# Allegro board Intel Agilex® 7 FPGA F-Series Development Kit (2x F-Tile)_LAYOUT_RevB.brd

Outline 254 x 111.15 mm; copper layers: TOP, L02_GND1, L03_SIG1, L04_GND2, L05_SIG2, L06_GND3, L07_SIG3, L08_GND4, L09_PWR1, L10_PWR2, L11_GND5, L12_SIG4, L13_GND6, L14_SIG5, L15_GND7, L16_SIG6, L17_GND8, BOTTOM. Coordinates in mm from the lower left corner of the outline.
Outline path: 0,111.15 0,4.5 15,4.5 15,12.75 33.35,12.75 33.35,4.5 41.35,4.5 41.35,10.92 arc(43.18,12.75) 45,10.92 45,0.5 45.5,0 55.7,0 56.2,0.5 56.2,7.45 arc(57.15,8.4) 58.1,7.45 58.1,0.5 58.6,0 128.8,0 129.3,0.5 129.3,7.62 arc(130.67,8.99) 132.04,7.62 132.04,3.45 132.55,2.95 143.35,2.95 144.74,5.32 144.74,7.95 140.78,7.95 arc(139.54,8.46) 139.03,9.7 139.03,11 arc(139.54,12.24) 140.78,12.75 254,12.75 254,111.15 0,111.15

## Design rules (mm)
constraint set DEFAULT: min track width 0.149
net group BMC_BUF_TCK: nets BMC_BUF_TCK N754986
net group BMC_BUF_TDI: nets BMC_BUF_TDI N755042
net group BMC_BUF_TMS: nets BMC_BUF_TMS N754746
net group CIPRI_HIGH_REFCLK_N: nets CIPRI_HIGH_REFCLK_N R_CIPRI_HIGH_REFCLK_N
net group CIPRI_HIGH_REFCLK_P: nets CIPRI_HIGH_REFCLK_P R_CIPRI_HIGH_REFCLK_P
net group CIPRI_LOW_REFCLK_N: nets CIPRI_LOW_REFCLK_N R_CIPRI_LOW_REFCLK_N
net group CIPRI_LOW_REFCLK_P: nets CIPRI_LOW_REFCLK_P R_CIPRI_LOW_REFCLK_P
net group CLK_100M_CXL_CONN_C_N: nets CLK_100M_CXL_CONN_C_N CLK_CXL_CONN_N
net group CLK_100M_CXL_CONN_C_P: nets CLK_100M_CXL_CONN_C_P CLK_CXL_CONN_P
net group CLK_CXL_EP_N: nets CLK_CXL_EP_N SI2204_OUT1N
net group CLK_CXL_EP_P: nets CLK_CXL_EP_P SI2204_OUT1P
net group CLK_FPGA_100M_N: nets CLK_FPGA_100M_N R_CLK_FPGA_100M_N
net group CLK_FPGA_100M_P: nets CLK_FPGA_100M_P R_CLK_FPGA_100M_P
net group CXL_TX_C_N0: nets CXL_TX_C_N0 CXL_TX_N0
net group CXL_TX_C_N1: nets CXL_TX_C_N1 CXL_TX_N1
net group CXL_TX_C_N2: nets CXL_TX_C_N2 CXL_TX_N2
net group CXL_TX_C_N3: nets CXL_TX_C_N3 CXL_TX_N3
net group CXL_TX_C_P0: nets CXL_TX_C_P0 CXL_TX_P0
net group CXL_TX_C_P1: nets CXL_TX_C_P1 CXL_TX_P1
net group CXL_TX_C_P2: nets CXL_TX_C_P2 CXL_TX_P2
net group CXL_TX_C_P3: nets CXL_TX_C_P3 CXL_TX_P3
net group DDR4_COMP_REFCLK_N: nets DDR4_COMP_REFCLK_N R_DDR4_COMP_REFCLK_N
net group DDR4_COMP_REFCLK_P: nets DDR4_COMP_REFCLK_P R_DDR4_COMP_REFCLK_P
net group DDR4_DIMM1_BYTE7: nets DDR4_DIMM1_DQ57 DDR4_DIMM1_DQ63
net group DDR4_DIMM1_REFCLK_N: nets DDR4_DIMM1_REFCLK_N R_DDR4_DIMM1_REFCLK_N
net group DDR4_DIMM1_REFCLK_P: nets DDR4_DIMM1_REFCLK_P R_DDR4_DIMM1_REFCLK_P
net group DDR4_DIMM1_TDQS_N9: nets DDR4_DIMM1_DBI_N0 DDR4_DIMM1_TDQS_N9
net group DDR4_DIMM1_TDQS_N10: nets DDR4_DIMM1_DBI_N1 DDR4_DIMM1_TDQS_N10
net group DDR4_DIMM1_TDQS_N11: nets DDR4_DIMM1_DBI_N2 DDR4_DIMM1_TDQS_N11
net group DDR4_DIMM1_TDQS_N12: nets DDR4_DIMM1_DBI_N3 DDR4_DIMM1_TDQS_N12
net group DDR4_DIMM1_TDQS_N13: nets DDR4_DIMM1_DBI_N4 DDR4_DIMM1_TDQS_N13
net group DDR4_DIMM1_TDQS_N14: nets DDR4_DIMM1_DBI_N5 DDR4_DIMM1_TDQS_N14
net group DDR4_DIMM1_TDQS_N15: nets DDR4_DIMM1_DBI_N6 DDR4_DIMM1_TDQS_N15
net group DDR4_DIMM1_TDQS_N16: nets DDR4_DIMM1_DBI_N7 DDR4_DIMM1_TDQS_N16
net group DDR4_DIMM1_TDQS_N17: nets DDR4_DIMM1_DBI_N8 DDR4_DIMM1_TDQS_N17
net group DDR4_DIMM2_REFCLK_N: nets DDR4_DIMM2_REFCLK_N R_DDR4_DIMM2_REFCLK_N
net group DDR4_DIMM2_REFCLK_P: nets DDR4_DIMM2_REFCLK_P R_DDR4_DIMM2_REFCLK_P
net group DDR4_DIMM2_TDQS_N9: nets DDR4_DIMM2_DBI_N0 DDR4_DIMM2_TDQS_N9
net group DDR4_DIMM2_TDQS_N10: nets DDR4_DIMM2_DBI_N1 DDR4_DIMM2_TDQS_N10
net group DDR4_DIMM2_TDQS_N11: nets DDR4_DIMM2_DBI_N2 DDR4_DIMM2_TDQS_N11
net group DDR4_DIMM2_TDQS_N12: nets DDR4_DIMM2_DBI_N3 DDR4_DIMM2_TDQS_N12
net group DDR4_DIMM2_TDQS_N13: nets DDR4_DIMM2_DBI_N4 DDR4_DIMM2_TDQS_N13
net group DDR4_DIMM2_TDQS_N14: nets DDR4_DIMM2_DBI_N5 DDR4_DIMM2_TDQS_N14
net group DDR4_DIMM2_TDQS_N15: nets DDR4_DIMM2_DBI_N6 DDR4_DIMM2_TDQS_N15
net group DDR4_DIMM2_TDQS_N16: nets DDR4_DIMM2_DBI_N7 DDR4_DIMM2_TDQS_N16
net group DDR4_DIMM2_TDQS_N17: nets DDR4_DIMM2_DBI_N8 DDR4_DIMM2_TDQS_N17
net group DDR4_RESET_ALERET: nets DDR4_COMP_ALERT_N DDR4_COMP_RESET_N
net group DIM_RESET_ALERET_1: nets DDR4_DIMM1_ALERT_N DDR4_DIMM1_RESET_N
net group DIM_RESET_ALERET_2: nets DDR4_DIMM2_ALERT_N DDR4_DIMM2_RESET_N
net group DP_DDR4_DIMM1_DQS_0: nets DDR4_DIMM1_DQS_N0 DDR4_DIMM1_DQS_P0
net group DP_DDR4_DIMM1_DQS_1: nets DDR4_DIMM1_DQS_N1 DDR4_DIMM1_DQS_P1
net group DP_DDR4_DIMM1_DQS_2: nets DDR4_DIMM1_DQS_N2 DDR4_DIMM1_DQS_P2
net group DP_DDR4_DIMM1_DQS_3: nets DDR4_DIMM1_DQS_N3 DDR4_DIMM1_DQS_P3
net group DP_DDR4_DIMM1_DQS_4: nets DDR4_DIMM1_DQS_N4 DDR4_DIMM1_DQS_P4
net group DP_DDR4_DIMM1_DQS_5: nets DDR4_DIMM1_DQS_N5 DDR4_DIMM1_DQS_P5
net group DP_DDR4_DIMM1_DQS_6: nets DDR4_DIMM1_DQS_N6 DDR4_DIMM1_DQS_P6
net group DP_DDR4_DIMM1_DQS_7: nets DDR4_DIMM1_DQS_N7 DDR4_DIMM1_DQS_P7
net group DP_DDR4_DIMM1_DQS_8: nets DDR4_DIMM1_DQS_N8 DDR4_DIMM1_DQS_P8
net group DP_DDR4_DIMM2_DQS_0: nets DDR4_DIMM2_DQS_N0 DDR4_DIMM2_DQS_P0
net group DP_DDR4_DIMM2_DQS_1: nets DDR4_DIMM2_DQS_N1 DDR4_DIMM2_DQS_P1
net group DP_DDR4_DIMM2_DQS_2: nets DDR4_DIMM2_DQS_N2 DDR4_DIMM2_DQS_P2
net group DP_DDR4_DIMM2_DQS_3: nets DDR4_DIMM2_DQS_N3 DDR4_DIMM2_DQS_P3
net group DP_DDR4_DIMM2_DQS_4: nets DDR4_DIMM2_DQS_N4 DDR4_DIMM2_DQS_P4
net group DP_DDR4_DIMM2_DQS_5: nets DDR4_DIMM2_DQS_N5 DDR4_DIMM2_DQS_P5
net group DP_DDR4_DIMM2_DQS_6: nets DDR4_DIMM2_DQS_N6 DDR4_DIMM2_DQS_P6
net group DP_DDR4_DIMM2_DQS_7: nets DDR4_DIMM2_DQS_N7 DDR4_DIMM2_DQS_P7
net group DP_DDR4_DIMM2_DQS_8: nets DDR4_DIMM2_DQS_N8 DDR4_DIMM2_DQS_P8
net group DP_FPGA_TEMPDIODE0C: nets FPGA_TEMPDIODE0CN FPGA_TEMPDIODE0CP
net group DP_FX2_D_: nets FX2_D_N FX2_D_P
net group DP_INLET_TEMP_: nets INLET_TEMP_N INLET_TEMP_P
net group DP_OUTLET_TEMP_: nets OUTLET_TEMP_N OUTLET_TEMP_P
net group DP_PCIE_REFCLK_: nets REFCLK_PCIE_EP_EDGE_N REFCLK_PCIE_EP_EDGE_P
net group DP_PEX_RX_0: nets PCIE_EP_TX_N0 PCIE_EP_TX_P0
net group DP_PEX_RX_1: nets PCIE_EP_TX_N1 PCIE_EP_TX_P1
net group DP_PEX_RX_2: nets PCIE_EP_TX_N2 PCIE_EP_TX_P2
net group DP_PEX_RX_3: nets PCIE_EP_TX_N3 PCIE_EP_TX_P3
net group DP_PEX_RX_4: nets PCIE_EP_TX_N4 PCIE_EP_TX_P4
net group DP_PEX_RX_5: nets PCIE_EP_TX_N5 PCIE_EP_TX_P5
net group DP_PEX_RX_6: nets PCIE_EP_TX_N6 PCIE_EP_TX_P6
net group DP_PEX_RX_7: nets PCIE_EP_TX_N7 PCIE_EP_TX_P7
net group DP_PEX_RX_8: nets PCIE_EP_TX_N8 PCIE_EP_TX_P8
net group DP_PEX_RX_9: nets PCIE_EP_TX_N9 PCIE_EP_TX_P9
net group DP_PEX_RX_10: nets PCIE_EP_TX_N10 PCIE_EP_TX_P10
net group DP_PEX_RX_11: nets PCIE_EP_TX_N11 PCIE_EP_TX_P11
net group DP_PEX_RX_12: nets PCIE_EP_TX_N12 PCIE_EP_TX_P12
net group DP_PEX_RX_13: nets PCIE_EP_TX_N13 PCIE_EP_TX_P13
net group DP_PEX_RX_14: nets PCIE_EP_TX_N14 PCIE_EP_TX_P14
net group DP_PEX_RX_15: nets PCIE_EP_TX_N15 PCIE_EP_TX_P15
net group F_CLK_FPGA_100M_N: nets F_CLK_FPGA_100M_N F_CLK_FPGA_100M_P
net group FLASH0_1V8_CLK: nets FLASH0_1V8_CLK N2830995
net group FLASH1_1V8_CLK: nets FLASH1_1V8_CLK N2830997
net group FM6_TEMP3: nets FPGA_TEMP3N FPGA_TEMP3P
net group FPGA_1V2_AVSTX16_CLK: nets FPGA_1V2_AVSTX16_CLK N2831570
net group FPGA_1V8_ASX4_CLK: nets FPGA_1V8_ASX4_CLK N227760
net group FPGA_GNDSENSE: nets FPGA_GNDSENSE FPGA_VCCLSENSE
net group FPGA_RCVD_CLK1_REFOUT_N: nets FPGA_RCVD_CLK1_REFOUT_N N1703311
net group FPGA_RCVD_CLK1_REFOUT_P: nets FPGA_RCVD_CLK1_REFOUT_P N1703298
net group FPGA_RCVD_CLK2_REFOUT_N: nets FPGA_RCVD_CLK2_REFOUT_N N1703337
net group FPGA_RCVD_CLK2_REFOUT_P: nets FPGA_RCVD_CLK2_REFOUT_P N1703324
net group FPGA_TEMP0A: nets FPGA_TEMP0AN FPGA_TEMP0AP
net group FPGA_TEMP4: nets FPGA_TEMP4N FPGA_TEMP4P
net group FPGA_VCC_HSSI_SENSE: nets FPGA_VCC_HSSI_GNDSENSE FPGA_VCC_HSSI_SENSE
net group HPS_GPIO31: nets HPS_SCL N748119
net group N6295719: nets N6295710 N6295719
net group N6296326: nets N6296130 N6296326
net group N6296367: nets N6296322 N6296367
net group N6365365: nets N6365353 N6365365
net group N6438706: nets N6295800 N6438706
net group N6992523: nets N6992519 N6992523
net group N6993090: nets N6993090 N6993094
net group N6998281: nets N6647874 N6998281
net group N6999941: nets N6649352 N6999941
net group NIOS_CLK: nets N2830778 NIOS_CLK
net group PCIE_EP_JTAG_TDO: nets N754798 PCIE_EP_JTAG_TDO
net group PCIE_EP_RX_CN0: nets PCIE_EP_RX_CN0 PCIE_EP_RX_N0
net group PCIE_EP_RX_CN1: nets PCIE_EP_RX_CN1 PCIE_EP_RX_N1
net group PCIE_EP_RX_CN2: nets PCIE_EP_RX_CN2 PCIE_EP_RX_N2
net group PCIE_EP_RX_CN3: nets PCIE_EP_RX_CN3 PCIE_EP_RX_N3
net group PCIE_EP_RX_CN4: nets PCIE_EP_RX_CN4 PCIE_EP_RX_N4
net group PCIE_EP_RX_CN5: nets PCIE_EP_RX_CN5 PCIE_EP_RX_N5
net group PCIE_EP_RX_CN6: nets PCIE_EP_RX_CN6 PCIE_EP_RX_N6
net group PCIE_EP_RX_CN7: nets PCIE_EP_RX_CN7 PCIE_EP_RX_N7
net group PCIE_EP_RX_CN8: nets PCIE_EP_RX_CN8 PCIE_EP_RX_N8
net group PCIE_EP_RX_CN9: nets PCIE_EP_RX_CN9 PCIE_EP_RX_N9
net group PCIE_EP_RX_CN10: nets PCIE_EP_RX_CN10 PCIE_EP_RX_N10
net group PCIE_EP_RX_CN11: nets PCIE_EP_RX_CN11 PCIE_EP_RX_N11
net group PCIE_EP_RX_CN12: nets PCIE_EP_RX_CN12 PCIE_EP_RX_N12
net group PCIE_EP_RX_CN13: nets PCIE_EP_RX_CN13 PCIE_EP_RX_N13
net group PCIE_EP_RX_CN14: nets PCIE_EP_RX_CN14 PCIE_EP_RX_N14
net group PCIE_EP_RX_CN15: nets PCIE_EP_RX_CN15 PCIE_EP_RX_N15
net group PCIE_EP_RX_CP0: nets PCIE_EP_RX_CP0 PCIE_EP_RX_P0
net group PCIE_EP_RX_CP1: nets PCIE_EP_RX_CP1 PCIE_EP_RX_P1
net group PCIE_EP_RX_CP2: nets PCIE_EP_RX_CP2 PCIE_EP_RX_P2
net group PCIE_EP_RX_CP3: nets PCIE_EP_RX_CP3 PCIE_EP_RX_P3
net group PCIE_EP_RX_CP4: nets PCIE_EP_RX_CP4 PCIE_EP_RX_P4
net group PCIE_EP_RX_CP5: nets PCIE_EP_RX_CP5 PCIE_EP_RX_P5
net group PCIE_EP_RX_CP6: nets PCIE_EP_RX_CP6 PCIE_EP_RX_P6
net group PCIE_EP_RX_CP7: nets PCIE_EP_RX_CP7 PCIE_EP_RX_P7
net group PCIE_EP_RX_CP8: nets PCIE_EP_RX_CP8 PCIE_EP_RX_P8
net group PCIE_EP_RX_CP9: nets PCIE_EP_RX_CP9 PCIE_EP_RX_P9
net group PCIE_EP_RX_CP10: nets PCIE_EP_RX_CP10 PCIE_EP_RX_P10
net group PCIE_EP_RX_CP11: nets PCIE_EP_RX_CP11 PCIE_EP_RX_P11
net group PCIE_EP_RX_CP12: nets PCIE_EP_RX_CP12 PCIE_EP_RX_P12
net group PCIE_EP_RX_CP13: nets PCIE_EP_RX_CP13 PCIE_EP_RX_P13
net group PCIE_EP_RX_CP14: nets PCIE_EP_RX_CP14 PCIE_EP_RX_P14
net group PCIE_EP_RX_CP15: nets PCIE_EP_RX_CP15 PCIE_EP_RX_P15
net group PTP_SAMPLE_CLK_250M_N: nets C_PTP_SAMPLE_CLK_250M_N PTP_SAMPLE_CLK_250M_N
net group PTP_SAMPLE_CLK_250M_P: nets C_PTP_SAMPLE_CLK_250M_P PTP_SAMPLE_CLK_250M_P
net group QSFP_REFCLK_N: nets C_QSFP_REFCLK_N QSFP_REFCLK_N
net group QSFP_REFCLK_P: nets C_QSFP_REFCLK_P QSFP_REFCLK_P
net group QSFPDD_REFCLK_N: nets C_QSFPDD_REFCLK_N QSFPDD_REFCLK_N
net group QSFPDD_REFCLK_P: nets C_QSFPDD_REFCLK_P QSFPDD_REFCLK_P
net group REFCLK_CXL_CONN_N: nets BUF2_Q0_N REFCLK_CXL_CONN_N
net group REFCLK_CXL_CONN_P: nets BUF2_Q0_P REFCLK_CXL_CONN_P
net group REFCLK_CXL_EP_N: nets BUF2_Q1_N REFCLK_CXL_EP_N
net group REFCLK_CXL_EP_P: nets BUF2_Q1_P REFCLK_CXL_EP_P
net group REFCLK_CXL_RP_N: nets REFCLK_CXL_RP_N SI2204_OUT2N
net group REFCLK_CXL_RP_P: nets REFCLK_CXL_RP_P SI2204_OUT2P
net group REFCLK_PCIE_13A_CH2_N: nets BUF1_Q1_N REFCLK_PCIE_13A_CH2_N
net group REFCLK_PCIE_13A_CH2_P: nets BUF1_Q1_P REFCLK_PCIE_13A_CH2_P
net group REFCLK_PCIE_13A_CH5_N: nets BUF1_Q0_N REFCLK_PCIE_13A_CH5_N
net group REFCLK_PCIE_13A_CH5_P: nets BUF1_Q0_P REFCLK_PCIE_13A_CH5_P
net group REFCLK_PCIE_EP_N: nets REFCLK_PCIE_EP_N SI2204_OUT0N
net group REFCLK_PCIE_EP_P: nets REFCLK_PCIE_EP_P SI2204_OUT0P
net group TOD_MASTER_CLK_125M_N: nets C_TOD_MASTER_CLK_125M_N TOD_MASTER_CLK_125M_N
net group TOD_MASTER_CLK_125M_P: nets C_TOD_MASTER_CLK_125M_P TOD_MASTER_CLK_125M_P
net group USB_T_CLK: nets N1009759 USB_T_CLK
net group VSENSE0+: nets VSENSE0+ VSENSE0-
net group 5MILS: nets FPGA_VCC_PG
net group 10 MIL: nets N1428757 N6365028 N6365052 N6366923 POWER_ON
net group 42.5 OHM OUT: nets PCIE_EP_PRSNT_NX1 PCIE_EP_PRSNT_NX4 PCIE_EP_PRSNT_NX8 PCIE_EP_PRSNT_NX16 PCIE_RSV2 PCIE_RSV4 PCIE_RSV5 PCIE_RSV6 PCIE_RSV7
net group AVST: nets FPGA_1V2_AVSTX16_D0 FPGA_1V2_AVSTX16_D1 FPGA_1V2_AVSTX16_D2 FPGA_1V2_AVSTX16_D3 FPGA_1V2_AVSTX16_D4 FPGA_1V2_AVSTX16_D5 FPGA_1V2_AVSTX16_D6 FPGA_1V2_AVSTX16_D7 FPGA_1V2_AVSTX16_D8 FPGA_1V2_AVSTX16_D9 FPGA_1V2_AVSTX16_D10 FPGA_1V2_AVSTX16_D11 FPGA_1V2_AVSTX16_D12 FPGA_1V2_AVSTX16_D13 FPGA_1V2_AVSTX16_D14 FPGA_1V2_AVSTX16_D15 FPGA_1V2_AVSTX16_READY FPGA_1V2_AVSTX16_VALID
net group CLK_SE: nets FPGA_OSC_CLK1 FX2_SCL FX2_SDA GPIO1_3V3_AC1_PTP_CLK_LOL MAX10_50MHZ_CLK PCIE_3V3_EP_CLKREQN PCIE_3V3_EP_SMBCLK PPS_FPGA_CLKOUT PTP_CLK_RST_N SEL_CXL_REFCLK SEL_PCIE_REFCLK SHARE_CLK ZL_OSC_CLK
net group DDR4_COMP_ADDR: nets DDR4_COMP_A0 DDR4_COMP_A1 DDR4_COMP_A2 DDR4_COMP_A3 DDR4_COMP_A4 DDR4_COMP_A5 DDR4_COMP_A6 DDR4_COMP_A7 DDR4_COMP_A8 DDR4_COMP_A9 DDR4_COMP_A10 DDR4_COMP_A11 DDR4_COMP_A12 DDR4_COMP_A13 DDR4_COMP_A14 DDR4_COMP_A15 DDR4_COMP_A16 DDR4_COMP_ACT_N DDR4_COMP_BA0 DDR4_COMP_BA1 DDR4_COMP_BG0 DDR4_COMP_BG1 DDR4_COMP_CKE DDR4_COMP_CS_N DDR4_COMP_ODT DDR4_COMP_PAR DDR4_COMP_RZQ DDR4_COMP_TEN
net group DDR4_COMP_DATA3: nets DDR4_COMP_DBI_N3 DDR4_COMP_DQS_N3 DDR4_COMP_DQS_P3
net group DDR4_DIMM1_ADDR: nets DDR4_DIMM1_A0 DDR4_DIMM1_A1 DDR4_DIMM1_A2 DDR4_DIMM1_A3 DDR4_DIMM1_A4 DDR4_DIMM1_A5 DDR4_DIMM1_A6 DDR4_DIMM1_A7 DDR4_DIMM1_A8 DDR4_DIMM1_A9 DDR4_DIMM1_A10 DDR4_DIMM1_A11 DDR4_DIMM1_A12 DDR4_DIMM1_A13 DDR4_DIMM1_A14 DDR4_DIMM1_A15 DDR4_DIMM1_A16 DDR4_DIMM1_A17 DDR4_DIMM1_ACT_N DDR4_DIMM1_BA0 DDR4_DIMM1_BA1 DDR4_DIMM1_BG0 DDR4_DIMM1_BG1 DDR4_DIMM1_C0 DDR4_DIMM1_C1 DDR4_DIMM1_CKE0 DDR4_DIMM1_CKE1 DDR4_DIMM1_CS_N0 DDR4_DIMM1_CS_N1 DDR4_DIMM1_ODT0 DDR4_DIMM1_ODT1 DDR4_DIMM1_PAR DDR4_DIMM1_SA0 DDR4_DIMM1_SA1 DDR4_DIMM1_SA2
net group DDR4_DIMM1_BYTE0: nets DDR4_DIMM1_DQ0 DDR4_DIMM1_DQ4 DDR4_DIMM1_DQ5 DDR4_DIMM1_DQ6 DDR4_DIMM1_DQ7
net group DDR4_DIMM1_BYTE8: nets DDR4_DIMM1_DQ64 DDR4_DIMM1_DQ68 DDR4_DIMM1_DQ70
net group DDR4_DIMM2_ADDR: nets DDR4_DIMM2_A0 DDR4_DIMM2_A1 DDR4_DIMM2_A2 DDR4_DIMM2_A3 DDR4_DIMM2_A4 DDR4_DIMM2_A5 DDR4_DIMM2_A6 DDR4_DIMM2_A7 DDR4_DIMM2_A8 DDR4_DIMM2_A9 DDR4_DIMM2_A10 DDR4_DIMM2_A11 DDR4_DIMM2_A12 DDR4_DIMM2_A13 DDR4_DIMM2_A14 DDR4_DIMM2_A15 DDR4_DIMM2_A16 DDR4_DIMM2_A17 DDR4_DIMM2_ACT_N DDR4_DIMM2_BA0 DDR4_DIMM2_BA1 DDR4_DIMM2_BG0 DDR4_DIMM2_BG1 DDR4_DIMM2_C0 DDR4_DIMM2_C1 DDR4_DIMM2_CKE0 DDR4_DIMM2_CKE1 DDR4_DIMM2_CS_N0 DDR4_DIMM2_CS_N1 DDR4_DIMM2_ODT0 DDR4_DIMM2_ODT1 DDR4_DIMM2_PAR DDR4_DIMM2_SA0 DDR4_DIMM2_SA1 DDR4_DIMM2_SA2
net group DDR4_DIMM2_BYTE8: nets DDR4_DIMM2_DQ64 DDR4_DIMM2_DQ66 DDR4_DIMM2_DQ68 DDR4_DIMM2_DQ70
net group DDR_CLK: nets DDR4_COMP_CK_N DDR4_COMP_CK_P DDR4_DIMM1_CK_N0 DDR4_DIMM1_CK_N1 DDR4_DIMM1_CK_P0 DDR4_DIMM1_CK_P1 DDR4_DIMM2_CK_N0 DDR4_DIMM2_CK_N1 DDR4_DIMM2_CK_P0 DDR4_DIMM2_CK_P1
net group FLASH0_QSPI: nets FLASH0_1V8_CSN FLASH0_1V8_DATA0 FLASH0_1V8_DATA1 FLASH0_1V8_DATA2 FLASH0_1V8_DATA3 FLASH0_1V8_RESETN
net group FLASH1_QSPI: nets FLASH1_1V8_CSN FLASH1_1V8_DATA0 FLASH1_1V8_DATA1 FLASH1_1V8_DATA2 FLASH1_1V8_DATA3 FLASH1_1V8_RESETN
net group FPGA_JTAG: nets FPGA_1V8_JTAG_TCK FPGA_1V8_JTAG_TDI FPGA_1V8_JTAG_TDO FPGA_1V8_JTAG_TMS
net group GND: nets FPGA_VCC_HSSI_GND
net group HIGH_NOISE: nets N93250 N2975570 SW0 SW1 SW2 SW3 SW4
net group HPS_GPIO30: nets HPS_SDA
net group LOW_NOISE: nets 0V6_DDR4_VREF_DIMM 3V3_AGND 3V3_QSFP 3V3_QSFPDD N6231213 N6231502 N6646840 N6648304 PCIE_VDD_1V85 QSFP_VCC QSFP_VCCR QSFP_VCCT QSFPDD_VCC QSFPDD_VCCR QSFPDD_VCCT U94_INTVCC VDDIO_ZL30733 VDDO0_ZL30733 VDDO1_ZL30733 VDDO3_ZL30733 VDDO4_ZL30733 VDDO5_ZL30733 VDDO6_ZL30733 VDDO7_ZL30733 VDDO8_ZL30733 VDDO9_ZL30733
net group MG_CXL_RX: nets CXL_RX_N0 CXL_RX_N1 CXL_RX_N2 CXL_RX_N3 CXL_RX_P0 CXL_RX_P1 CXL_RX_P2 CXL_RX_P3
net group MG_QSFP_RX: nets QSFP_TX0_N QSFP_TX0_P QSFP_TX1_N QSFP_TX1_P QSFP_TX2_N QSFP_TX2_P QSFP_TX3_N QSFP_TX3_P
net group MG_QSFP_TX: nets QSFP_RX0_N QSFP_RX0_P QSFP_RX1_N QSFP_RX1_P QSFP_RX2_N QSFP_RX2_P QSFP_RX3_N QSFP_RX3_P
net group MG_QSFPDD_RX: nets QSFPDD_RX0_N QSFPDD_RX0_P QSFPDD_RX1_N QSFPDD_RX1_P QSFPDD_RX2_N QSFPDD_RX2_P QSFPDD_RX3_N QSFPDD_RX3_P QSFPDD_RX4_N QSFPDD_RX4_P QSFPDD_RX5_N QSFPDD_RX5_P QSFPDD_RX6_N QSFPDD_RX6_P QSFPDD_RX7_N QSFPDD_RX7_P
net group MG_QSFPDD_TX: nets QSFPDD_TX0_N QSFPDD_TX0_P QSFPDD_TX1_N QSFPDD_TX1_P QSFPDD_TX2_N QSFPDD_TX2_P QSFPDD_TX3_N QSFPDD_TX3_P QSFPDD_TX4_N QSFPDD_TX4_P QSFPDD_TX5_N QSFPDD_TX5_P QSFPDD_TX6_N QSFPDD_TX6_P QSFPDD_TX7_N QSFPDD_TX7_P
net group NIOS_SPI: nets NIOS_CSN NIOS_IO0 NIOS_IO1 NIOS_IO2 NIOS_IO3
net group SENSE: nets IREF ISENSE0 ISENSE1 ISENSE2 ISENSE3 ISENSE4 N6440564 N6440883 N6648020 N6649494 PWM0 PWM1 PWM2 PWM3 PWM4 TSNS0 TSNS1

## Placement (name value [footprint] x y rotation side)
B1  UE36-C16221-06A3A  [QSFPDD_CAGE_UE36-C16221-06A3A]  40.99 36.06 90 top
B2  U95-T1C1-101A  [ZQSFP_CAGE_U95-T1C1-101A]  29.4 57.85 90 top
BT1  CR1620 Holder  [16MM_BAT_HOLDER]  208.54 63.71 180 top
C1  0.22uF  [SMC0201IA]  62.83 10.73 270 bottom
C2  0.22uF  [SMC0201IA]  63.49 10.73 270 bottom
C6  0.22uF  [SMC0201IA]  67.83 10.73 270 bottom
C7  0.22uF  [SMC0201IA]  68.49 10.73 270 bottom
C8  0.22uF  [SMC0201IA]  71.83 10.73 270 bottom
C9  0.22uF  [SMC0201IA]  72.49 10.73 270 bottom
C10  0.22uF  [SMC0201IA]  75.83 10.73 270 bottom
C11  0.22uF  [SMC0201IA]  76.49 10.73 270 bottom
C12  0.22uF  [SMC0201IA]  81.83 10.73 270 bottom
C13  0.22uF  [SMC0201IA]  82.49 10.73 270 bottom
C14  0.22uF  [SMC0201IA]  85.83 10.73 270 bottom
C15  0.22uF  [SMC0201IA]  86.49 10.73 270 bottom
C16  1pF  [0402]  59.19 11 180 top
C17  1pF  [0402]  65.03 11 0 bottom
C18  0.22uF  [SMC0201IA]  89.83 10.73 270 bottom
C19  1pF  [0402]  74.18 12.65 90 top
C20  0.22uF  [SMC0201IA]  90.49 10.73 270 bottom
C21  1pF  [0402]  77.73 11 0 bottom
C22  1pF  [0402]  79.64 11 0 bottom
C23  1pF  [0402]  125.48 11 180 top
C24  0.22uF  [SMC0201IA]  93.83 10.73 270 bottom
C25  1pF  [0402]  97.54 11 0 bottom
C26  0.22uF  [SMC0201IA]  94.49 10.73 270 bottom
C27  1pF  [0402]  61.35 11 180 top
C28  1pF  [0402]  77.86 11 180 top
C29  1pF  [0402]  95.77 11 180 top
C30  1pF  [0402]  121.55 11 180 top
C31  0.22uF  [SMC0201IA]  98.83 10.73 270 bottom
C32  0.22uF  [SMC0201IA]  99.49 10.73 270 bottom
C33  0.22uF  [SMC0201IA]  102.83 10.73 270 bottom
C34  0.22uF  [SMC0201IA]  103.49 10.73 270 bottom
C35  0.22uF  [SMC0201IA]  106.83 10.73 270 bottom
C36  0.22uF  [SMC0201IA]  107.49 10.73 270 bottom
C37  0.1uF  [0402]  42.17 19.89 0 bottom
C38  0.22uF  [SMC0201IA]  110.83 10.73 270 bottom
C39  0.22uF  [SMC0201IA]  111.49 10.73 270 bottom
C40  0.22uF  [SMC0201IA]  114.83 10.73 270 bottom
C41  0.22uF  [SMC0201IA]  115.49 10.73 270 bottom
C42  0.22uF  [SMC0201IA]  118.83 10.73 270 bottom
C43  0.22uF  [SMC0201IA]  119.49 10.73 270 bottom
C44  0.22uF  [SMC0201IA]  122.83 10.73 270 bottom
C45  0.22uF  [SMC0201IA]  123.49 10.73 270 bottom
C46  0.22uF  [SMC0201IA]  126.83 10.73 270 bottom
C47  0.22uF  [SMC0201IA]  127.49 10.73 270 bottom
C48  0.1uF  [0402]  26.82 92.26 270 bottom
C49  0.1uF  [0402]  36.32 92.26 90 bottom
C50  1uF  [0402]  34.42 92.26 270 bottom
C51  1uF  [0402]  28.7 92.26 90 bottom
C52  10uF  [0402]  16.14 70.94 270 bottom
C53  0.1uF  [0402]  25.68 75.65 90 bottom
C54  0.1uF  [0402]  28.18 77.15 180 bottom
C55  0.1uF  [0402]  29.68 78.65 270 bottom
C56  0.1uF  [0402]  27.68 74.65 270 bottom
C57  0.1uF  [0402]  28.68 75.65 270 bottom
C58  0.1uF  [0402]  25.18 77.15 0 bottom
C59  0.1uF  [0402]  27.18 77.15 0 bottom
C60  0.1uF  [0402]  25.68 74.65 270 bottom
C61  0.1uF  [0402]  31.68 73.65 270 bottom
C62  0.1uF  [0402]  24.18 71.15 180 bottom
C63  0.1uF  [0402]  23.18 71.15 180 bottom
C64  10uF  [0402]  24.18 85.05 180 bottom
C65  0.1uF  [0402]  26.18 71.15 180 bottom
C66  0.1uF  [0402]  31.18 78.15 0 bottom
C67  0.1uF  [0402]  18.18 78.15 180 bottom
C68  0.1uF  [0402]  35.69 82.63 270 bottom
C69  0.1uF  [0402]  27.18 71.15 180 bottom
C70  0.1uF  [0402]  35.98 80.15 0 bottom
C71  0.1uF  [0402]  21.68 77.65 90 bottom
C72  0.1uF  [0402]  28.18 81.15 0 bottom
C73  0.1uF  [0402]  25.18 81.15 0 bottom
C74  0.1uF  [0402]  18.18 74.15 180 bottom
C75  0.1uF  [0402]  28.18 85.05 0 bottom
C76  0.1uF  [0402]  18.18 76.15 180 bottom
C77  0.1uF  [0402]  26.18 80.15 180 bottom
C78  0.1uF  [0402]  29.18 71.15 180 bottom
C79  0.1uF  [0402]  23.63 67.78 90 bottom
C80  0.1uF  [0402]  35.57 81.61 270 bottom
C81  0.1uF  [0402]  32.68 77.65 270 bottom
C82  0.1uF  [0402]  35.98 78.15 0 bottom
C83  0.1uF  [0402]  22.18 76.15 180 bottom
C84  0.1uF  [0402]  21.92 79.05 0 bottom
C85  0.1uF  [0402]  31.68 76.65 270 bottom
C86  0.1uF  [0402]  28.18 71.15 180 bottom
C87  0.1uF  [0402]  23.59 94.78 90 bottom
C88  0.1uF  [0402]  22.18 71.15 180 bottom
C89  0.1uF  [0402]  31.18 71.15 180 bottom
C90  0.1uF  [0402]  31.18 81.15 0 bottom
C91  0.1uF  [0402]  22.92 79.88 45 bottom
C92  10uF  [0402]  37.35 81.6 90 bottom
C93  0.1uF  [0402]  31.68 79.65 270 bottom
C94  0.1uF  [0402]  23.79 80.24 45 bottom
C95  0.1uF  [0402]  30.18 80.15 0 bottom
C96  0.1uF  [0402]  30.18 72.15 180 bottom
C97  0.1uF  [0402]  22.68 72.65 90 bottom
C98  0.1uF  [0402]  11.18 72.85 270 bottom
C99  0.1uF  [0402]  25.18 53.8 270 bottom
C100  0.1uF  [0402]  25.18 54.82 270 bottom
C101  0.1uF  [0402]  72.27 80.09 90 top
C107  0.1uF  [0402]  59.89 103.71 90 bottom
C108  10uF  [0402]  83.78 37.16 90 bottom
C109  0.47uF  [0402]  83.19 37.6 180 top
C110  10uF  [0402]  74.68 79.33 270 bottom
C111  0.47uF  [0402]  84.72 76.66 90 bottom
C112  1uF  [0201]  87.73 65.78 210 bottom
C113  1uF  [0201]  86.33 64.97 30 bottom
C114  1uF  [0201]  115.62 59.8 210 bottom
C115  1uF  [0201]  115.01 58.88 150 bottom
C116  47uF  [0603]  70.49 72.72 270 bottom
C117  47uF  [0603]  72.14 72.72 270 bottom
C118  22uF  [0603]  72.27 75.9 270 bottom
C119  47uF  [0603]  72.7 55.32 90 bottom
C120  47uF  [0603]  75.45 53.29 270 bottom
C121  22uF  [0603]  74.43 63.96 0 bottom
C122  0.1uF  [0402]  108.14 61.47 0 bottom
C123  47UF  [1206]  79 37.42 0 top
C124  22uF  [1206]  82.81 33.35 270 bottom
C125  22uF  [1206]  84.46 33.35 270 top
C126  47uF  [0603]  97.04 36.02 270 top
C127  47uF  [0603]  97.04 36.15 270 bottom
C128  22uF  [0603]  100.97 36.15 90 bottom
C132  10nF  [0402]  128.42 98.4 180 bottom
C133  0.1uF  [0402]  124.88 95.58 0 bottom
C134  10nF  [0402]  129.15 95.56 0 bottom
C135  0.1uF  [0402]  106.18 95.56 0 bottom
C136  10nF  [0402]  101.13 95.58 0 bottom
C137  0.1uF  [0402]  107.05 98.4 180 bottom
C138  10nF  [0402]  103.64 95.56 0 bottom
C139  0.1uF  [0402]  108.75 95.56 0 bottom
C140  10nF  [0402]  111.29 99.52 0 bottom
C141  0.1uF  [0402]  109.56 99.49 0 bottom
C142  10nF  [0402]  104.51 98.4 180 bottom
C143  0.1uF  [0402]  122.34 95.58 0 bottom
C144  100uF  [1206]  111.67 97.36 0 bottom
C145  1uF  [0402]  115.2 99.9 270 bottom
C146  100uF  [1206]  100.24 98.3 0 bottom
C147  100uF  [1206]  132.5 98.55 180 bottom
C148  10uF  [1210_H2P2MM]  95.03 96.95 180 bottom
C149  10uF  [1210_H2P2MM]  132.5 95.76 0 bottom
C150  0.1uF  [0402]  124.04 98.4 180 bottom
C151  0.1uF  [0402]  122.11 98.4 180 bottom
C152  0.1uF  [0402]  51.34 100.03 270 bottom
C153  0.1uF  [0402]  115.2 98.63 270 bottom
C154  10nF  [0402]  126.48 98.4 180 bottom
C155  10nF  [0402]  126.59 95.58 0 bottom
C156  10nF  [0402]  115.23 94.06 270 bottom
C157  0.1uF  [0402]  49.44 100.03 90 bottom
C158  10nF  [0402]  175.8 98.12 180 bottom
C159  0.1uF  [0402]  115.23 95.33 270 bottom
C160  100uF  [1206]  172.25 98 0 bottom
C161  10nF  [0402]  174.99 95.57 0 bottom
C162  0.1uF  [0402]  175.93 95.57 0 bottom
C166  10nF  [0402]  129.15 103.18 0 bottom
C167  0.1uF  [0402]  124.04 106.02 180 bottom
C168  10nF  [0402]  128.42 106.02 180 bottom
C169  0.1uF  [0402]  107.05 106.02 180 bottom
C170  10nF  [0402]  101.13 103.2 0 bottom
C171  0.1uF  [0402]  106.18 103.18 0 bottom
C172  10nF  [0402]  104.51 106.02 180 bottom
C173  0.1uF  [0402]  108.75 103.18 0 bottom
C174  10nF  [0402]  103.64 103.18 0 bottom
C175  0.1uF  [0402]  109.56 107.11 0 bottom
C176  10nF  [0402]  111.29 107.14 0 bottom
C177  0.1uF  [0402]  122.11 106.02 180 bottom
C178  100uF  [1206]  111.67 104.98 0 bottom
C179  1uF  [0402]  115.2 107.52 270 bottom
C180  100uF  [1206]  100.24 105.92 0 bottom
C181  100uF  [1206]  132.5 106.17 180 bottom
C182  10uF  [1210_H2P2MM]  95.03 104.57 180 bottom
C183  10uF  [1210_H2P2MM]  132.5 103.38 0 bottom
C184  0.1uF  [0402]  124.88 103.2 0 bottom
C185  0.1uF  [0402]  122.34 103.2 0 bottom
C186  10nF  [0402]  126.48 106.02 180 bottom
C187  0.1uF  [0402]  51.34 107.65 270 bottom
C188  10nF  [0402]  126.59 103.2 0 bottom
C189  0.1uF  [0402]  115.23 102.95 270 bottom
C190  10nF  [0402]  115.23 101.68 270 bottom
C191  0.1uF  [0402]  49.44 107.65 90 bottom
C192  100uF  [1206]  172.25 105.62 0 bottom
C193  10nF  [0402]  175.8 105.74 180 bottom
C194  0.1uF  [0402]  115.2 106.25 270 bottom
C195  0.1uF  [0402]  175.93 103.19 0 bottom
C196  10nF  [0402]  174.99 103.19 0 bottom
C197  0.1uF  [0402]  122.56 20.86 90 bottom
C198  0.1uF  [0402]  110.36 20.86 90 bottom
C199  0.47uF  [0402]  129.76 18.56 270 bottom
C200  0.47uF  [0402]  122.56 26.56 90 bottom
C201  22uF  [0603]  125.46 28.36 270 bottom
C202  0.47uF  [0402]  110.36 26.56 90 bottom
C203  0.47uF  [0402]  117.56 18.56 270 bottom
C204  22uF  [0603]  113.26 28.36 270 bottom
C205  2.2nF  [0402]  117.56 20.06 90 bottom
C206  2.2nF  [0402]  123.86 26.96 0 bottom
C207  2.2nF  [0402]  129.76 20.06 90 bottom
C208  2.2nF  [0402]  111.66 26.96 0 bottom
C209  2.2nF  [0402]  128.16 25.66 270 bottom
C210  2.2nF  [0402]  110.36 22.56 270 bottom
C211  2.2nF  [0402]  128.96 24.26 270 bottom
C212  2.2nF  [0402]  123.36 24.26 90 bottom
C213  2.2nF  [0402]  115.96 25.66 270 bottom
C214  3.3nF  [0402]  114.66 26.96 0 bottom
C215  3.3nF  [0402]  126.86 26.96 0 bottom
C216  4.7nF  [0402]  126.86 24.56 0 bottom
C217  4.7nF  [0402]  122.56 22.56 270 bottom
C218  4.7nF  [0402]  114.66 24.56 0 bottom
C219  0.47uF  [0402]  122.56 27.46 90 bottom
C220  0.47uF  [0402]  111.16 24.26 90 bottom
C221  0.47uF  [0402]  129.76 17.66 270 bottom
C222  22uF  [0603]  125.46 25.26 270 bottom
C223  22uF  [0603]  113.26 25.26 270 bottom
C224  1uF  [0402]  122.56 21.73 90 bottom
C225  1uF  [0402]  110.36 21.73 90 bottom
C226  0.01uF  [0402]  110.76 18.16 180 bottom
C227  0.01uF  [0402]  122.96 18.16 180 bottom
C228  0.01uF  [0402]  109.96 23.43 90 bottom
C229  0.1uF  [0402]  122.56 25.66 90 bottom
C230  0.1uF  [0402]  117.96 23.43 270 bottom
C231  0.1uF  [0402]  110.36 25.66 90 bottom
C232  0.1uF  [0402]  130.16 23.43 270 bottom
C233  0.47uF  [0402]  117.56 17.66 270 bottom
C234  0.47uF  [0402]  117.16 21.36 0 bottom
C235  0.47uF  [0402]  116.36 26.96 0 bottom
C236  0.47uF  [0402]  117.66 25.66 270 bottom
C237  0.47uF  [0402]  116.76 24.26 270 bottom
C238  0.47uF  [0402]  128.56 26.96 0 bottom
C239  0.47uF  [0402]  122.16 23.43 90 bottom
C240  0.47uF  [0402]  129.36 21.36 0 bottom
C241  0.47uF  [0402]  110.36 27.46 90 bottom
C242  0.47uF  [0402]  129.86 25.66 270 bottom
C243  0.1uF  [0402]  98.17 20.86 90 bottom
C244  0.1uF  [0402]  85.98 20.86 90 bottom
C245  0.47uF  [0402]  98.17 26.56 90 bottom
C246  0.47uF  [0402]  105.37 18.56 270 bottom
C247  22uF  [0603]  101.07 28.36 270 bottom
C248  0.47uF  [0402]  93.18 18.56 270 bottom
C249  0.47uF  [0402]  85.98 26.56 90 bottom
C250  22uF  [0603]  88.88 28.36 270 bottom
C251  2.2nF  [0402]  104.57 24.26 270 bottom
C252  2.2nF  [0402]  103.77 25.66 270 bottom
C253  2.2nF  [0402]  99.47 26.96 0 bottom
C254  2.2nF  [0402]  105.37 20.06 90 bottom
C255  2.2nF  [0402]  98.97 24.26 90 bottom
C256  2.2nF  [0402]  91.58 25.66 270 bottom
C257  2.2nF  [0402]  87.28 26.96 0 bottom
C258  2.2nF  [0402]  93.18 20.06 90 bottom
C259  2.2nF  [0402]  85.98 22.56 270 bottom
C260  3.3nF  [0402]  102.47 26.96 0 bottom
C261  3.3nF  [0402]  90.28 26.96 0 bottom
C262  4.7nF  [0402]  102.47 24.56 0 bottom
C263  4.7nF  [0402]  98.17 22.56 270 bottom
C264  4.7nF  [0402]  90.28 24.56 0 bottom
C265  0.47uF  [0402]  105.47 25.66 270 bottom
C266  0.47uF  [0402]  104.17 26.96 0 bottom
C267  0.47uF  [0402]  98.17 27.46 90 bottom
C268  22uF  [0603]  88.88 25.26 270 bottom
C269  22uF  [0603]  101.07 25.26 270 bottom
C270  1uF  [0402]  85.98 21.73 90 bottom
C271  1uF  [0402]  98.17 21.73 90 bottom
C272  0.01uF  [0402]  85.58 23.43 90 bottom
C273  0.01uF  [0402]  85.98 18.56 90 bottom
C274  0.01uF  [0402]  98.57 18.16 180 bottom
C275  0.1uF  [0402]  85.98 25.66 90 bottom
C276  0.1uF  [0402]  93.58 23.43 270 bottom
C277  0.1uF  [0402]  98.17 25.66 90 bottom
C278  0.1uF  [0402]  105.77 23.43 270 bottom
C279  0.47uF  [0402]  104.97 21.36 0 bottom
C280  0.47uF  [0402]  105.37 17.66 270 bottom
C281  0.47uF  [0402]  97.77 23.43 90 bottom
C282  0.47uF  [0402]  92.78 21.36 0 bottom
C283  0.47uF  [0402]  92.38 24.26 270 bottom
C284  0.47uF  [0402]  93.18 17.66 270 bottom
C285  0.47uF  [0402]  93.28 25.66 270 bottom
C286  0.47uF  [0402]  86.78 24.26 90 bottom
C287  0.47uF  [0402]  85.98 27.46 90 bottom
C288  0.47uF  [0402]  91.98 26.96 0 bottom
C289  0.1uF  [0402]  72.81 20.96 90 bottom
C290  0.47uF  [0402]  81.19 18.16 180 bottom
C291  0.47uF  [0402]  73.79 26.56 90 bottom
C292  22uF  [0603]  76.69 26.96 270 bottom
C293  0.01uF  [0402]  77.99 26.16 0 bottom
C295  0.1uF  [0402]  216.92 30.05 270 top
C296  22uF  [1206]  202.83 23.32 90 bottom
C297  10uF  [0402]  199.65 30.81 180 top
C298  10uF  [0402]  200.67 30.81 180 top
C299  10uF  [0402]  218.96 19.38 90 top
C300  0.1uF  [0402]  202.7 30.81 180 top
C301  0.1uF  [0402]  201.68 30.81 180 top
C302  0.1uF  [0402]  216.92 19.38 270 top
C303  12pF  [0402]  210.22 22.6 0 bottom
C304  22uF  [0603]  36.13 31.5 270 bottom
C305  1uF  [0402]  36.8 28.72 0 bottom
C306  0.1uF  [0402]  35.8 28.72 0 bottom
C307  0.1uF  [0402]  44.97 24.87 0 bottom
C308  22uF  [0603]  45.22 27.41 90 bottom
C309  0.1uF  [0402]  57.54 25.5 180 bottom
C310  10uF  [0402]  55.89 25.5 0 bottom
C311  22uF  [0603]  54.11 23.85 90 bottom
C312  22uF  [0603]  51.82 23.09 90 bottom
C313  0.1uF  [0402]  51.57 27.76 0 bottom
C314  10uF  [0402]  50.43 27.76 180 bottom
C315  22uF  [0603]  47.76 28.17 0 bottom
C316  22uF  [0603]  47.76 26.65 0 bottom
C317  0.1uF  [0402]  58.3 28.68 0 bottom
C318  10uF  [0402]  56.9 29.19 180 bottom
C319  22uF  [0603]  51.57 32.36 90 bottom
C320  22uF  [0603]  53.6 28.43 0 bottom
C321  1000pF  [1206]  6.99 35.07 90 bottom
C322  22uF  [0603]  27 44.62 270 bottom
C323  1uF  [0402]  27.67 41.97 0 bottom
C324  0.1uF  [0402]  26.67 41.97 0 bottom
C325  0.1uF  [0402]  36.65 45.83 90 bottom
C326  22uF  [0603]  36.71 50.12 180 bottom
C327  0.1uF  [0402]  48.54 48.48 90 bottom
C328  10uF  [0402]  42.31 43.9 180 bottom
C329  22uF  [0603]  39.5 44.02 270 bottom
C330  22uF  [0603]  41.03 44.02 270 bottom
C331  0.1uF  [0402]  43.75 47.63 0 bottom
C332  10uF  [0402]  42.32 47.13 0 bottom
C333  22uF  [0603]  39.5 47.2 90 bottom
C334  22uF  [0603]  41.03 47.2 90 bottom
C335  0.1uF  [0402]  48.54 49.49 90 bottom
C336  10uF  [0402]  39.37 51.56 0 bottom
C337  22uF  [0603]  42.31 51.56 90 bottom
C338  22uF  [0603]  40.72 51.56 90 bottom
C339  1000pF  [1206]  5.21 57.23 90 bottom
C340  0.22uF  [SMC0201IA]  14.95 84.86 180 top
C341  0.22uF  [SMC0201IA]  14.95 84.2 180 top
C342  0.22uF  [SMC0201IA]  12.97 83.06 180 top
C343  0.22uF  [SMC0201IA]  12.97 82.4 180 top
C344  1uF  [0402]  29.73 64.34 180 bottom
C345  0.1uF  [0402]  28.84 64.34 0 bottom
C346  0.1uF  [0402]  37.78 67.39 180 bottom
C347  0.22uF  [SMC0201IA]  14.95 77.66 180 top
C348  0.22uF  [SMC0201IA]  14.95 77 180 top
C349  0.22uF  [SMC0201IA]  12.97 75.86 180 top
C350  0.22uF  [SMC0201IA]  12.97 75.2 180 top
C351  1uF  [0402]  70.11 43.89 180 bottom
C352  1uF  [0402]  71 47.32 270 bottom
C353  1uF  [0402]  60.08 46.31 180 bottom
C354  10uF  [0402]  58.3 46.31 180 bottom
C355  1uF  [0402]  59.19 46.31 180 bottom
C356  1uF  [0402]  61.86 46.31 180 bottom
C357  10uF  [0402]  60.97 46.31 180 bottom
C358  1uF  [0402]  59.82 43.77 180 bottom
C359  1uF  [0402]  58.55 47.7 90 bottom
C360  10uF  [0402]  62.75 46.31 180 bottom
C361  1uF  [0402]  58.55 48.59 90 bottom
C362  1uF  [0402]  66.49 48.34 270 bottom
C363  10uF  [0402]  56.27 47.7 180 bottom
C364  1uF  [0402]  52.71 45.29 270 bottom
C365  1uF  [0402]  63.63 46.31 180 bottom
C366  1uF  [0402]  62.36 43.77 180 bottom
C367  1uF  [0402]  68.46 51.58 0 bottom
C368  1uF  [0402]  58.55 50.37 90 bottom
C369  10uF  [0402]  56.27 50.5 180 bottom
C370  10uF  [0402]  55.25 54.18 180 bottom
C371  1uF  [0402]  58.55 51.39 90 bottom
C372  1uF  [0402]  68.52 53.04 270 bottom
C373  1uF  [0402]  68.59 45.54 270 bottom
C374  1uF  [0402]  68.59 46.56 270 bottom
C375  10uF  [0402]  70.75 55.07 90 bottom
C376  1uF  [0402]  68.21 60.78 270 bottom
C377  1uF  [0402]  64.52 46.31 180 bottom
C378  10uF  [0402]  65.41 46.31 180 bottom
C379  1uF  [0402]  66.56 43.77 180 bottom
C380  1uF  [0402]  56.4 59.26 90 bottom
C381  10uF  [0402]  54.36 55.07 0 bottom
C382  1uF  [0402]  56.01 56.47 0 bottom
C383  0.1uF  [0402]  56.9 56.47 0 bottom
C384  1uF  [0402]  66.3 46.31 180 bottom
C385  10uF  [0402]  67.19 46.31 180 bottom
C386  1uF  [0402]  69.1 43.89 180 bottom
C387  0.1uF  [0402]  62.36 41.86 0 top
C388  0.1uF  [0402]  61.35 41.86 0 top
C389  0.1uF  [0402]  65.29 57.48 180 top
C390  0.1uF  [0402]  64.27 57.48 180 top
C391  0.1uF  [0402]  69.35 57.48 180 top
C392  0.1uF  [0402]  68.33 57.48 180 top
C393  0.1uF  [0402]  67.32 57.48 180 top
C394  10uF  [0402]  67.19 52.78 0 bottom
C395  1uF  [0402]  66.81 55.32 0 bottom
C396  0.1uF  [0402]  66.3 57.48 180 top
C397  1uF  [0402]  66.3 52.78 0 bottom
C398  1uF  [0402]  64.52 52.78 0 bottom
C399  10uF  [0402]  65.41 52.78 0 bottom
C400  1uF  [0402]  64.27 55.32 0 bottom
C401  1uF  [0402]  63.63 52.78 0 bottom
C402  10uF  [0402]  62.75 52.78 0 bottom
C403  1uF  [0402]  61.73 55.32 0 bottom
C404  1uF  [0402]  61.86 52.78 0 bottom
C405  10uF  [0402]  60.97 52.78 0 bottom
C406  1uF  [0402]  59.44 58.05 180 bottom
C407  1uF  [0402]  60.08 52.78 0 bottom
C408  10uF  [0402]  59.19 52.78 0 bottom
C409  1uF  [0402]  58.17 59.26 270 bottom
C410  18pF  [0402]  9.66 43.13 270 bottom
C411  18pF  [0402]  7.88 43.13 90 bottom
C412  1uF  [0402]  12.71 53.65 90 bottom
C413  1uF  [0402]  6.1 42.24 270 bottom
C414  1uF  [0402]  4.33 42.24 270 bottom
C415  0.1uF  [0402]  7.25 53.04 0 bottom
C416  0.1uF  [0402]  12.71 47.7 270 bottom
C417  0.1uF  [0402]  6.1 43.13 90 bottom
C418  0.1uF  [0402]  4.33 43.13 90 bottom
C420  1uF  [0402]  16.64 27.26 270 bottom
C421  1uF  [0402]  16.64 30.18 270 bottom
C422  1uF  [0402]  16.64 23.45 270 bottom
C423  1uF  [0402]  25.53 32.46 180 bottom
C424  1uF  [0402]  20.96 32.46 180 bottom
C432  1uF  [0402]  22.87 53.29 180 bottom
C433  1uF  [0402]  19.95 53.29 180 bottom
C434  1uF  [0402]  16.14 53.29 180 bottom
C435  1uF  [0402]  25.15 48.97 90 bottom
C436  1uF  [0402]  25.15 44.4 90 bottom
C444  0.1uF  [0402]  59.06 13.41 270 bottom
C449  0.1uF  [0402]  52.08 13.41 270 bottom
C450  100pf  [0402]  63.66 77.71 90 top
C451  0.1uF  [0402]  63.25 79.2 180 bottom
C452  100pf  [0402]  65.56 77.71 90 top
C453  100pf  [0402]  66.96 80.88 180 top
C456  0.1uF  [0402]  90.69 37.54 90 bottom
C457  100pf  [0402]  88.75 36.38 0 top
C458  100pf  [0402]  88.75 34.47 0 top
C459  100pf  [0402]  91.93 33.07 90 top
C460  0.1uF  [0402]  162.82 95.84 90 bottom
C461  0.1uF  [0402]  162.82 105.62 90 bottom
C466  0.1uF  [0402]  194.7 64.47 180 bottom
C467  0.1uF  [0402]  194.7 61.67 180 bottom
C470  0.1uF  [0402]  73.03 98.5 0 bottom
C471  0.1uF  [0402]  64.52 98.12 0 bottom
C472  0.1uF  [0402]  65.82 103.61 90 bottom
C473  0.1uF  [0402]  75.06 103.71 180 bottom
C482  1000pF  [0402]  212.48 104.6 90 bottom
C483  1000pF  [0402]  216.73 104.45 90 bottom
C484  1000pF  [1206]  241.82 106.89 180 bottom
C485  1000pF  [0402]  221.05 104.45 90 bottom
C486  1000pF, DNI  [0402]  223.78 105.04 0 bottom
C487  0.1uF  [0402]  224.44 60.58 90 bottom
C488  0.1uF  [0402]  37.22 83.01 0 bottom
C489  0.1uF  [0402]  28.84 25.35 270 bottom
C490  0.1uF  [0402]  9.15 97.36 90 bottom
C491  0.1uF  [0402]  23.09 97.59 270 bottom
C492  4.7nF  [0402]  7.37 98.86 270 bottom
C493  12pF  [0402]  11.13 93.61 0 top
C494  12pF  [0402]  11.13 95.46 180 top
C495  22uF  [0603]  12.58 100.28 270 top
C496  0.1uF  [0402]  20.38 97.17 0 bottom
C497  0.1uF  [0402]  14.92 97.74 90 bottom
C498  0.1uF  [0402]  14.17 93.42 90 bottom
C499  0.1uF  [0402]  14.17 95.33 90 bottom
C500  0.1uF  [0402]  14.85 88.79 180 bottom
C501  0.1uF  [0402]  12.9 91.29 90 bottom
C502  0.1uF  [0402]  19.85 88.79 180 bottom
C503  0.1uF  [0402]  20.71 91.29 270 bottom
C504  100uF  [0805]  97.37 66.02 180 bottom
C505  100uF  [0805]  105.26 62.56 90 bottom
C506  100uF  [0805]  105.26 59.85 90 bottom
C507  100uF  [0805]  96.68 63.1 270 bottom
C508  100uF  [0805]  105.26 64.93 90 bottom
C509  100uF  [0805]  96.68 60.77 270 bottom
C510  47uF  [0603]  97.04 58.98 0 bottom
C511  47uF  [0603]  99.23 65.99 270 bottom
C512  47uF  [0603]  102.71 66.07 270 bottom
C513  47uF  [0603]  104.88 58.09 180 bottom
C514  100uF  [0805]  105.21 36.02 0 top
C515  100uF  [0805]  108.34 87.33 270 top
C516  100uF  [0805]  111.39 36.02 0 top
C517  100uF  [0805]  90.18 87.33 270 top
C518  47uF  [0603]  97.29 87.07 180 top
C519  47uF  [0603]  107.37 36.15 270 top
C520  47uF  [0603]  122.99 35.95 270 top
C521  47uF  [0603]  118.63 87.07 180 top
C522  47uF  [0805]  100.97 64.54 0 bottom
C523  47uF  [0805]  100.97 59.34 180 bottom
C524  10uF  [0402]  109.01 36.65 0 top
C525  1uF  [0201]  110.66 52.84 90 bottom
C526  22uF  [0603]  102.71 62.85 270 bottom
C527  22uF  [0603]  102.71 59.21 270 bottom
C528  22uF  [0603]  100.13 61.95 180 bottom
C529  22uF  [0603]  99.23 59.21 270 bottom
C530  1uF  [0201]  91.9 70.95 30 bottom
C533  10uF  [0402]  85.18 37.61 0 top
C534  10uF  [0402]  104.66 87.33 270 top
C535  10uF  [0402]  101.86 36.65 0 top
C536  10uF  [0402]  84.19 37.6 0 top
C537  10uF  [0402]  94.11 87.33 270 top
C538  10uF  [0402]  100.59 87.33 270 top
C539  10uF  [0402]  112.08 87.33 270 top
C540  10uF  [0402]  103.13 36.65 0 top
C541  10uF  [0402]  71 68.4 270 top
C542  1uF  [0201]  90.92 59.34 210 bottom
C543  1uF  [0201]  111.03 64.51 30 bottom
C544  1uF  [0201]  92.69 72.19 210 bottom
C545  4.7uF  [0402]  100.97 71.11 0 bottom
C546  4.7uF  [0402]  99.15 52.71 180 bottom
C548  10uF  [0402]  101.64 51.36 0 bottom
C549  10uF  [0402]  103.77 72.73 240 bottom
C550  1uF  [0201]  90.31 70.38 330 bottom
C551  1uF  [0201]  91.11 71.29 30 bottom
C552  1uF  [0201]  110.48 54.68 270 bottom
C561  1uF  [0201]  109.43 51.63 30 bottom
C562  1uF  [0201]  109.24 53.93 330 bottom
C571  1uF  [0201]  90.96 72.9 150 bottom
C572  4.7uF  [0402]  102.44 70.27 0 bottom
C573  4.7uF  [0402]  101.2 53.63 180 bottom
C574  10uF  [0402]  90.91 55.84 300 bottom
C575  10uF  [0402]  91 63.07 300 bottom
C576  10uF  [0402]  88.61 58.93 300 bottom
C577  10uF  [0402]  88.61 62.61 300 bottom
C578  10uF  [0402]  87.02 58.93 300 bottom
C579  10uF  [0402]  87.02 62.61 300 bottom
C580  47uF  [0805]  73.92 72.34 90 top
C581  47uF  [0805]  73.92 58.12 90 top
C582  10uF  [0402]  110.94 68.15 120 bottom
C583  10uF  [0402]  110.94 60.79 120 bottom
C584  10uF  [0402]  113.33 61.25 120 bottom
C585  10uF  [0402]  113.33 66.77 120 bottom
C586  10uF  [0402]  114.93 61.25 120 bottom
C587  10uF  [0402]  114.93 64.93 120 bottom
C588  47uF  [0805]  73.92 62.94 90 top
C589  47uF  [0805]  73.92 60.53 90 top
C590  47uF  [0805]  73.92 55.7 90 top
C591  47uF  [0805]  73.92 70.18 90 top
C592  100uF  [2917_4P3MM]  218.19 33.48 180 top
C593  100uF  [2917_4P3MM]  229.12 33.48 0 top
C594  22uF  [1206]  219.59 37.67 180 top
C595  22uF  [1206]  227.21 38.17 0 top
C596  22uF  [1206]  219.59 40.21 180 top
C597  22uF  [1206]  219.59 42.75 180 top
C598  0.1uF  [0402]  227.46 39.97 90 top
C599  1uF  [0402]  231.27 47.58 270 top
C600  0.1uF  [0402]  231.27 46.56 90 top
C601  0.01uF  [0402]  228.06 41.99 90 bottom
C602  0.22uF  [0402]  226.58 47.45 90 top
C603  0.1uF  [0402]  227.34 48.47 270 bottom
C604  10nF  [0402]  228.99 47.96 180 top
C605  15nF  [0402]  227.97 47.96 180 top
C606  0.1uF  [0402]  226.58 48.47 270 top
C607  DNI  [0603]  238.43 98.56 270 bottom
C608  DNI  [0603]  235.38 98.56 270 bottom
C609  4.7nF  [0402]  219.35 78.65 180 bottom
C614  1.5uF  [1206]  211.34 78.18 90 bottom
C615  560uF  [8MM_CAN]  236.99 98.63 180 top
C616  22uF  [1206]  226.7 84.24 180 bottom
C617  22uF  [1206]  226.7 87.04 180 bottom
C618  22uF  [1206]  226.61 89.23 180 top
C619  22uF  [1206]  226.61 86.31 180 top
C620  0.1uF  [0402]  226.7 84.53 270 top
C621  1uF  [0402]  223.27 77.8 90 top
C622  0.1uF  [0402]  223.27 76.79 270 top
C623  0.01uF  [0402]  225.81 79.16 90 bottom
C624  12pF  [0402]  242.2 70.06 90 top
C625  0.22uF  [0402]  227.97 76.91 270 top
C626  0.1uF  [0402]  225.39 74.66 270 top
C627  10nF  [0402]  225.56 76.41 0 top
C628  15nF  [0402]  226.58 76.41 0 top
C629  0.1uF  [0402]  227.97 75.9 90 top
C648  22uF  [0603]  29.6 97.74 0 top
C649  22uF  [0603]  38.74 98.88 180 bottom
C650  22uF  [0603]  13.09 66.63 0 bottom
C651  82pF  [0402]  35.31 99.58 0 top
C652  22uF  [0603]  32.27 94.82 0 bottom
C653  22uF  [0603]  32.65 97.74 0 top
C654  22uF  [0603]  32.27 96.47 0 bottom
C655  82pF  [0402]  31.5 98.69 180 bottom
C656  22uF  [0603]  35.69 95.84 180 bottom
C657  22uF  [0603]  35.69 98.88 180 bottom
C658  22uF  [0603]  35.69 97.36 180 bottom
C659  82pF  [0402]  20.07 64.34 0 bottom
C660  22uF  [0603]  16.14 68.15 0 bottom
C661  22uF  [0603]  16.14 66.63 0 bottom
C662  22uF  [0603]  16.14 69.67 0 bottom
C663  2.2nF  [0402]  32.21 103.62 0 top
C664  2.2nF  [0402]  36.62 104.68 90 bottom
C665  2.2nF  [0402]  13.69 61.47 270 bottom
C688  22uF  [1206]  36.45 105.45 180 top
C689  1nF  [0402]  31.38 105.23 0 bottom
C690  4.7uF  [0603]  184.03 60.02 180 top
C691  1uF  [0402]  184.79 58.24 180 top
C692  270uF  [PANASONIC_SVPC_8X12]  206.51 95.33 270 top
C693  2.2uF  [0402]  181.49 60.02 270 top
C694  2.2uF  [0402]  183.01 58.24 180 top
C695  270uF  [PANASONIC_SVPC_8X12]  238.39 55.96 0 top
C696  3.3nF  [0402]  178.34 48.6 90 top
C697  6800pF  [0402]  180.09 46.43 0 top
C698  6800pF  [0402]  174.76 60.53 180 top
C699  330pF  [0402]  179.2 46.43 0 top
C700  330pF  [0402]  173.87 60.53 180 top
C701  3.3nF  [0402]  177.1 56.72 270 bottom
C702  0.1uF  [0402]  156.73 35.64 90 top
C703  10uF  [1210_H2P2MM]  156.85 35.38 180 bottom
C704  10uF  [1210_H2P2MM]  156.85 38.94 180 bottom
C705  10uF  [1210_H2P2MM]  164.22 36.65 0 bottom
C706  10uF  [1210_H2P2MM]  164.22 37.42 0 top
C707  10uF  [1210_H2P2MM]  164.22 40.08 0 bottom
C708  47pF  [0402]  160.54 37.92 0 bottom
C709  10uF  [0603]  160.92 39.07 270 top
C710  1uF  [0402]  161.17 41.61 180 top
C711  0.1uF, DNI  [0402]  171.71 48.34 270 top
C712  0.47uF  [0603]  163.33 44.4 90 bottom
C713  47pF  [0402]  159.9 46.18 0 bottom
C714  10uF  [1210_H2P2MM]  156.85 42.5 180 bottom
C715  10uF  [1210_H2P2MM]  156.85 46.05 180 bottom
C716  10uF  [1210_H2P2MM]  164.22 47.7 0 bottom
C717  10uF  [1210_H2P2MM]  156.73 48.08 180 top
C718  10uF  [1210_H2P2MM]  164.22 48.47 0 top
C719  0.1uF  [0402]  156.73 46.05 270 top
C720  10uF  [1210_H2P2MM]  156.85 49.86 180 bottom
C721  10uF  [1210_H2P2MM]  156.85 53.42 180 bottom
C722  47pF  [0402]  160.54 52.4 0 bottom
C723  0.1uF  [0402]  156.73 50.12 90 top
C724  10uF  [1210_H2P2MM]  164.22 51.13 0 bottom
C725  10uF  [1210_H2P2MM]  164.22 51.89 0 top
C726  10uF  [1210_H2P2MM]  164.22 54.56 0 bottom
C727  10uF  [0603]  160.92 53.55 270 top
C728  1uF  [0402]  161.17 56.09 180 top
C729  0.1uF, DNI  [0402]  171.71 49.86 270 top
C730  0.47uF  [0603]  163.33 58.88 90 bottom
C731  47pF  [0402]  159.9 60.66 0 bottom
C732  10uF  [1210_H2P2MM]  156.85 56.97 180 bottom
C733  10uF  [1210_H2P2MM]  156.85 60.53 180 bottom
C734  10uF  [1210_H2P2MM]  164.22 62.18 0 bottom
C735  10uF  [1210_H2P2MM]  156.73 62.56 180 top
C736  10uF  [1210_H2P2MM]  164.22 62.94 0 top
C737  0.1uF  [0402]  156.73 60.53 270 top
C738  0.1uF  [0402]  156.73 64.59 90 top
C739  10uF  [1210_H2P2MM]  156.85 64.34 180 bottom
C740  10uF  [1210_H2P2MM]  156.85 67.9 180 bottom
C741  10uF  [1210_H2P2MM]  164.22 65.61 0 bottom
C742  47pF  [0402]  160.54 66.88 0 bottom
C743  10uF  [1210_H2P2MM]  164.22 66.37 0 top
C744  10uF  [1210_H2P2MM]  164.22 69.04 0 bottom
C745  10uF  [0603]  160.92 68.02 270 top
C746  1uF  [0402]  161.17 70.56 180 top
C747  0.1uF, DNI  [0402]  171.77 51.39 270 top
C748  0.47uF  [0603]  163.33 73.36 90 bottom
C749  47pF  [0402]  159.9 75.14 0 bottom
C750  10uF  [1210_H2P2MM]  156.85 71.45 180 bottom
C751  10uF  [1210_H2P2MM]  156.85 75.01 180 bottom
C752  10uF  [1210_H2P2MM]  164.22 76.66 0 bottom
C753  10uF  [1210_H2P2MM]  156.73 77.04 180 top
C754  10uF  [1210_H2P2MM]  164.22 77.42 0 top
C755  0.1uF  [0402]  156.73 75.01 270 top
C756  0.1uF  [0402]  156.73 79.07 90 top
C757  10uF  [1210_H2P2MM]  156.85 78.82 180 bottom
C758  10uF  [1210_H2P2MM]  156.85 82.37 180 bottom
C759  10uF  [1210_H2P2MM]  164.22 80.09 0 bottom
C760  10uF  [1210_H2P2MM]  164.22 80.85 0 top
C761  10uF  [1210_H2P2MM]  156.73 91.52 180 top
C762  47pF  [0402]  160.54 81.36 0 bottom
C763  10uF  [0603]  160.92 82.5 270 top
C764  1uF  [0402]  161.17 85.04 180 top
C765  0.1uF, DNI  [0402]  171.71 52.91 270 top
C766  0.47uF  [0603]  163.33 87.84 90 bottom
C767  47pF  [0402]  159.9 89.61 0 bottom
C768  10uF  [1210_H2P2MM]  156.85 85.93 180 bottom
C769  10uF  [1210_H2P2MM]  156.85 89.49 180 bottom
C770  10uF  [1210_H2P2MM]  164.22 91.52 0 bottom
C771  10uF  [1210_H2P2MM]  164.22 83.52 0 bottom
C772  10uF  [1210_H2P2MM]  164.22 91.52 0 top
C773  0.1uF  [0402]  156.73 89.49 270 top
C774  47pF  [0402]  160.54 23.32 0 bottom
C775  0.1uF  [0402]  156.73 21.03 90 top
C776  10uF  [1210_H2P2MM]  156.85 21.16 180 bottom
C777  10uF  [1210_H2P2MM]  156.85 24.72 180 bottom
C778  10uF  [1210_H2P2MM]  156.73 17.99 180 top
C779  10uF  [1210_H2P2MM]  156.85 17.73 180 bottom
C780  10uF  [1210_H2P2MM]  164.22 18.11 0 top
C781  10uF  [0603]  160.92 24.46 270 top
C782  1uF  [0402]  161.17 27 180 top
C783  0.1uF, DNI  [0402]  171.71 55.96 270 top
C784  0.47uF  [0603]  163.33 29.8 90 bottom
C785  47pF  [0402]  159.9 31.57 0 bottom
C786  10uF  [1210_H2P2MM]  156.85 28.27 180 bottom
C787  10uF  [1210_H2P2MM]  156.85 31.83 180 bottom
C788  10uF  [1210_H2P2MM]  164.22 33.23 0 bottom
C789  10uF  [1210_H2P2MM]  164.22 21.67 0 top
C790  10uF  [1210_H2P2MM]  164.22 33.61 0 top
C791  0.1uF  [0402]  156.73 31.45 270 top
C864  22uF  [0603]  210.83 39.58 180 top
C865  82pF  [0402]  204.35 36.97 180 top
C866  22uF  [0603]  207.78 39.58 180 top
C867  22uF  [0603]  207.78 41.1 180 bottom
C868  22uF  [0603]  207.78 41.1 180 top
C869  2.2nF  [0402]  210.35 33.53 270 top
C915  22uF  [0603]  201.05 39.58 180 top
C920  82pF  [0402]  194.57 36.97 180 top
C921  22uF  [0603]  198 39.58 180 top
C922  22uF  [0603]  198 41.1 180 bottom
C923  22uF  [0603]  198 41.1 180 top
C925  2.2nF  [0402]  200.57 33.53 270 top
C926  22uF  [0603]  192.67 95.07 180 top
C927  22uF  [0603]  140.72 21.16 270 top
C928  82pF  [0402]  186.06 92.73 180 top
C929  82pF  [0402]  143.07 15.45 270 top
C930  22uF  [0603]  189.62 95.07 180 top
C931  22uF  [0603]  189.62 95.07 180 bottom
C932  22uF  [0603]  189.62 96.6 180 top
C933  22uF  [0603]  140.72 18.11 270 top
C934  22uF  [0603]  137.68 18.11 270 top
C935  22uF  [0603]  139.2 18.11 270 top
C936  10nF  [0402]  192.06 89.92 270 top
C937  10nF  [0402]  146.69 20.53 0 top
C938  2.2uF  [0402]  194.19 100.15 0 top
C939  22uF  [0603]  187.03 102.44 90 bottom
C940  22uF  [0603]  188.7 105.49 270 bottom
C941  22uF  [0603]  187.03 102.44 90 top
C942  22uF  [0603]  190.38 105.49 270 top
C943  22uF  [0603]  187.03 105.49 270 top
C944  22uF  [0603]  187.03 105.49 270 bottom
C945  2.2uF  [0402]  63.63 14.81 270 top
C946  22uF  [0603]  65.67 21.85 0 top
C947  22uF  [0603]  67.7 17.73 90 bottom
C948  22uF  [0603]  69.22 17.48 90 bottom
C949  22uF  [0603]  68.71 20.3 180 top
C950  22uF  [0603]  68.71 18.62 180 top
C951  22uF  [0603]  68.71 21.85 180 top
C952  22uF  [0603]  193.68 105.49 270 top
C953  22uF  [0603]  192.01 105.49 270 top
C954  22uF  [0603]  68.71 17 180 top
C955  22uF  [0603]  68.71 15.32 180 top
C956  22uF  [0603]  190.38 105.49 270 bottom
C957  22uF  [0603]  69.48 22.3 270 bottom
C958  0.1uF  [0402]  187.52 98.76 270 top
C959  22uF  [0603]  188.7 105.49 270 top
C960  22uF  [0603]  67.95 22.3 270 bottom
C961  0.1uF  [0402]  63.38 21.35 180 top
C962  10nF  [0402]  195.08 102.57 0 top
C963  10nF  [0402]  66.05 13.92 270 top
C966  2.2nF  [0402]  81.39 23.43 270 bottom
C967  2.2nF  [0402]  79.69 26.96 0 bottom
C968  2.2nF  [0402]  73.79 25.66 90 bottom
C969  2.2nF  [0402]  79.39 25.66 270 bottom
C970  2.2nF  [0402]  73.79 27.46 90 bottom
C971  3.3nF  [0402]  81.09 25.66 270 bottom
C972  3.3nF  [0402]  74.59 24.26 90 bottom
C973  4.7nF  [0402]  80.19 24.26 270 bottom
C974  4.7nF  [0402]  72.81 23.43 90 bottom
C975  4.7nF  [0402]  75.09 26.96 0 bottom
C976  22uF  [0603]  67.19 68.02 90 top
C977  82pF  [0402]  65.35 73.74 90 top
C978  22uF  [0603]  67.44 71.07 90 bottom
C979  22uF  [0603]  65.92 71.07 90 bottom
C980  22uF  [0603]  67.19 71.07 90 top
C981  2.2nF  [0402]  61.73 68.66 180 top
C982  22uF  [0603]  67.19 60.15 90 top
C983  82pF  [0402]  65.35 65.86 90 top
C984  22uF  [0603]  67.19 63.2 90 bottom
C985  22uF  [0603]  68.71 63.2 90 top
C986  22uF  [0603]  67.19 63.2 90 top
C987  2.2nF  [0402]  61.73 60.78 180 top
C988  1uF  [0402]  12.71 45.67 90 bottom
C989  1uF  [0402]  12.71 51.64 90 bottom
C990  0.1uF  [0402]  12.71 46.69 270 bottom
C991  0.1uF  [0402]  12.71 50.75 270 bottom
C992  0.1uF  [0402]  2.55 51.51 90 bottom
C993  0.1uF  [0402]  16.64 29.29 90 bottom
C994  0.1uF  [0402]  21.85 32.46 0 bottom
C995  0.1uF  [0402]  16.64 24.34 90 bottom
C996  0.1uF  [0402]  24.65 32.46 0 bottom
C997  0.1uF  [0402]  16.64 26.37 90 bottom
C998  0.1uF  [0402]  17.03 53.29 0 bottom
C999  0.1uF  [0402]  19.06 53.29 0 bottom
C1000  0.1uF  [0402]  25.15 45.29 270 bottom
C1001  0.1uF  [0402]  25.15 48.08 270 bottom
C1002  0.1uF  [0402]  21.98 53.29 0 bottom
C1003  1000pF  [0402]  230.26 106 180 bottom
C1008  0.1uF  [0402]  72.17 52.46 270 top
C1009  0.1uF  [0402]  72.17 53.35 270 top
C1010  0.1uF  [0402]  72.17 48.9 270 top
C1011  0.1uF  [0402]  72.17 49.79 270 top
C1018  0.1uF  [0402]  222.13 99.01 90 bottom
C1019  0.1uF  [0402]  216.8 99.01 90 bottom
C1020  0.1uF  [0402]  209.3 99.01 90 bottom
C1021  0.1uF  [0402]  214.38 99.01 90 bottom
C1022  0.1uF  [0402]  10.93 25.48 270 bottom
C1023  0.1uF  [0402]  5.6 25.48 270 bottom
